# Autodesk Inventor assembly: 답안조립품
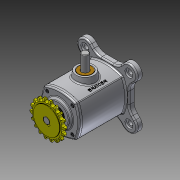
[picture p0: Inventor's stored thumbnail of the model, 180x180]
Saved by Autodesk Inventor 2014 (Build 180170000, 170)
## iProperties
Created: 2016-05
Part Number: 답안조립품
Document SubType Name: Assembly
Designer: J.H.CHAE
Author: J.H.CHAE
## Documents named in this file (11)
- C:\Users\Administrator\Desktop\460507v1017\답안조립품.iam
- C:\Users\Administrator\Desktop\460507v1017\본체.ipt
- C:\Users\Administrator\Desktop\460507v1017\M4x0.7x12.ipt
- C:\Users\Administrator\Desktop\460507v1017\베어링-6203.ipt
- C:\Users\Administrator\Desktop\460507v1017\부시.ipt
- C:\Users\Administrator\Desktop\460507v1017\스프로킷.ipt
- C:\Users\Administrator\Desktop\460507v1017\슬라이더.ipt
- C:\Users\Administrator\Desktop\460507v1017\오일실.ipt
- C:\Users\Administrator\Desktop\460507v1017\커버.ipt
- C:\Users\Administrator\Desktop\460507v1017\키5x5.ipt
- C:\Users\Administrator\Desktop\460507v1017\편심축.ipt
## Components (8 placed, 1 different names)
1. M4x0.7x12:1
2. M4x0.7x12:2
3. M4x0.7x12:3
4. M4x0.7x12:4
5. M4x0.7x12:5
6. M4x0.7x12:6
7. M4x0.7x12:7
8. M4x0.7x12:8
